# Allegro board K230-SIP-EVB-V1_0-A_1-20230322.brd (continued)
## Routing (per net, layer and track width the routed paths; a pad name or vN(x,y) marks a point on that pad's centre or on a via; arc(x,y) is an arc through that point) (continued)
VDD_5V: length 76.6
  TOP w0.305: v1(60.2,67.92) 60.35,68.07 61.09,68.07 ; v1(50.93,85.34) 50.55,85.72 R137.1 ; C145.1 v1(34.04,28.07) 34.04,28.45 34.58,29 U16.1 ; R35.2 v1(22.86,17.14) ; U6.3 45.97,27.82 ; R42.1 v1(10.92,47.75) ; R14.1 50.29,25.15 v1(50.16,25.02) ; R43.2 v1(10.92,52.07) ; v1(4.45,23.24) R3.1 ; R30.1 v1(40.39,26.29) ; U8.3 16.38,49.28 ; U30.6 60.02,129.34 v1(59.69,129.67) ; R15.1 v1(50.16,28.32) ; C284.2 v1(57.91,129.67) ; U15.4 37.97,45.66 v1(38.73,44.89) 38.93,44.7 C137.1 ; U9.3 65.65,65.28 ; R266.2 54.61,130.3 ; R5.1 64.26,28.96 ; U7.3 25.65,22.47 ; C283.2 v1(61.47,129.67) ; R28.2 v1(40.39,30.61)
  TOP w0.381: R8.2 v1(68.71,45.85) ; U27.5 v1(72.07,56.05) C273.2 ; R162.1 v1(70.17,53.21)
  ART03 w0.381: v1(60.2,67.92) 60.99,67.92 64.26,64.64 v1(64.26,63.88)
  BOTTOM w0.305: R23.2 53.34,46.11 ; v1(38.73,44.89) 39.37,44.26 39.37,41.53 38.99,41.15 38.99,30.81 ; U31.6 59.36,129.34 v1(59.69,129.67)
  BOTTOM w0.381: v1(50.93,85.34) 50.93,80.39 51.82,79.5 51.82,75.82 54.1,73.53 60.33,73.53 60.83,73.03 60.83,68.55 v1(60.2,67.92)
  vias: v1(9.14,117.47) v1(9.14,116.46) v1(14.86,47.75) v1(14.86,46.74) v1(14.86,45.47) v1(17.91,28.83) v1(17.91,27.94) v1(27.43,21.08) v1(28.7,21.08) v1(30.48,21.08) v1(33.91,18.16) v1(33.91,16.89) v1(33.91,15.62) v1(34.92,16.89) v1(44.58,26.42) v1(44.58,25.4) v1(44.58,24.38) v1(53.21,25.65) v1(53.21,24.64) v1(54.23,130.56) v1(54.23,46.1) v1(54.23,44.83) v1(54.23,43.56) v1(54.23,25.65) v1(54.23,24.64) v1(55.24,24.64) v1(55.5,130.56) v1(61.47,128.65) v1(64.26,62.87) v1(64.64,28.83) v1(64.64,27.69) v1(64.64,26.67) v1(65.02,45.09) v1(65.02,43.81) v1(65.02,42.55) v1(65.28,62.87)
VDD_5V_O: length 2.2
  TOP w0.305: J22.3 6.75,89.91 ; J22.4 6.76,90.41
  vias: v1(7.87,122.43) v1(7.87,121.16) v1(7.87,119.89) v1(49.53,135.89) v1(49.53,134.87) v1(50.93,135.89) v1(50.93,134.87)
3D_CTRL_IN: length 93.9
  TOP w0.076: 27.34,74.93 27.34,75.46 U19.P15
  TOP w0.127: J21.49 44.76,128.6 44.96,128.4 v1(47.88,128.4) ; 27.34,74.93 27.34,74.71 26.92,74.3 25.72,74.3 v3(24.89,75.12)
  ART03 w0.127: v3(24.89,75.12) 24.51,75.5 24.51,78.61 22.61,80.52 22.61,83.82 23.76,84.98 23.76,98.82 25.7,100.76 50.72,100.76 54.48,104.52 54.48,121.79 v1(47.88,128.4)
3D_CTRL_OUT1: length 94.1
  TOP w0.076: U19.P16 27.67,74.53 27.51,74.38
  TOP w0.127: v3(24.89,74.47) 25.45,73.91 27.05,73.91 27.51,74.38 ; v1(47.88,127.25) 45.59,127.25 44.26,128.59 J21.47
  ART03 w0.127: v3(24.89,74.47) 24.16,75.2 24.16,78.58 22.1,80.64 22.1,84.58 23.48,85.97 23.48,99.05 25.53,101.09 50.55,101.09 54.1,104.65 54.1,121.03 v1(47.88,127.25)
3D_CTRL_OUT2: length 105.3
  TOP w0.076: U19.P13 27.34,76.76 25.8,76.76
  TOP w0.127: J21.46 43.76,132.9 44.07,132.59 v1(44.2,132.59) ; v1(6.6,82.04) 6.6,76.07 8.38,74.3 11.43,74.3 12.06,73.66 13.97,73.66 14.76,74.45 22.89,74.45 25.2,76.76 25.8,76.76
  ART03 w0.127: v1(44.2,132.59) 43.94,132.84 40.77,132.84 38.77,130.85 38.77,116.75 36.45,114.43 26.54,114.43 13.34,101.22 13.34,99.06 12.24,97.97 12.24,91.53 9.91,89.19 9.91,86.61 7.62,84.33 7.62,83.06 v1(6.6,82.04)
ADC0: length 12.7
  TOP w0.127: U19.A7 36.88,80.99 37.95,82.05 39.51,82.05 41.66,84.2 44.96,84.2 v1(46.1,85.34)
  BOTTOM w0.127: v1(46.1,85.34) 46.1,86.23
ADC1: length 10
  TOP w0.127: U19.A6 36.72,81.64 42.2,87.12 v1(42.93,87.12)
  BOTTOM w0.127: R230.1 v1(42.93,87.12)
ADC2: length 65.7
  TOP w0.076: U19.B6 35.79,81.96 36.32,81.96
  TOP w0.127: v1(55.24,97.54) 45.34,87.63 42.31,87.63 36.64,81.96 36.32,81.96
  ART03 w0.127: v1(48.01,131.7) 48.01,130.18 55.24,122.94 v1(55.24,97.54)
  BOTTOM w0.127: v1(48.01,131.7) 48.01,132.59 R178.2
BOOT_CTL0: length 57.6
  TOP w0.127: v1(73.41,57.91) 74.8,57.91 74.93,57.78 SW1.1 ; U19.C14 v3(35.14,76.11)
  ART03 w0.127: v3(35.14,76.11) 35.49,76.45 48.01,76.45 48.77,75.69 62.36,75.69 62.74,76.07 63.93,76.07 69.85,70.15 69.85,65.28 73.41,61.72 73.41,59.82 73.91,59.31 73.91,58.42 v1(73.41,57.91)
  BOTTOM w0.127: v1(73.41,57.91) 73.41,57.28 TVS3.2 74.55,57.02 R99.1
BOOT_CTL1: length 62.7
  TOP w0.076: U19.C15 35.14,75.46 35.14,74.93 35.26,74.81
  TOP w0.127: 35.26,74.81 36.03,74.04 45.85,74.04 v1(47.62,75.82) ; SW1.2 77.47,57.91 76.33,59.05 v1(73.41,59.05)
  ART03 w0.127: v1(73.41,59.05) 73.03,59.44 73.03,61.47 69.47,65.02 69.47,70.13 64.54,75.06 56.52,75.06 56.13,74.68 49.15,74.68 48.01,75.82 v1(47.62,75.82)
  BOTTOM w0.127: v1(73.41,59.05) 74.17,59.05 TVS2.2 77.09,57.02 R101.1
CC1: length 7.8
  TOP w0.127: J1.A5 74.08,12.7 74.68,13.3 v1(74.68,14.22) 74.68,15.11 74.09,15.7 J1.B5
  BOTTOM w0.127: R1.1 v1(74.68,14.22)
CC_T: length 10.8
  TOP w0.127: R193.1 68.83,107.31 TVS7.1 69.35,105.91 J27.B5 73.21,105.91 74.17,104.95 74.17,103.5 73.57,102.91 J27.A5
CLK24M_XIN: length 16.8
  TOP w0.127: U19.A15 36.61,75.79 36.92,75.48 44.54,75.48 47.75,78.69 47.75,80.64 R97.2
CLK24M_XOUT: length 17
  TOP w0.076: 36.32,75.46 35.79,75.46 U19.B15
  TOP w0.127: 36.32,75.46 36.55,75.46 36.93,75.08 44.98,75.08 48.39,78.49 48.39,80.01 R105.2
CTRL0: length 26.8
  TOP w0.127: R170.2 v1(58.42,122.05) 58.42,122.43 58.71,122.72 U30.1
  ART03 w0.127: J36.1 57.91,98.55 57.91,121.54 v1(58.42,122.05)
CTRL1: length 29.1
  ART03 w0.127: v1(61.21,122.43) 58.29,119.51 58.29,100.46 J36.2
  BOTTOM w0.127: R171.2 61.21,121.41 v1(61.21,122.43) 60.67,122.98 U31.1
DDR_VREF: length 9.3
  TOP w0.254: U19.H11 v3(31.89,78.06)
  BOTTOM w0.305: C241.1 32,77.94 32.75,77.19 32.75,75.2 33.27,74.68 33.27,73.41 C240.1 C300.2 R95.2 R98.1
DEBUG_DM: length 25.6
  TOP w0.114: J27.A7 73.26,104.41 73.41,104.27 73.41,103.52 73.29,103.41 J27.B7 71.34,103.41 71.28,103.47 66.47,103.47 v1(66.13,103.12) ; v1(63.25,114.7) 63.47,114.47 63.47,114.02 R188.1
  BOTTOM w0.114: v1(63.25,114.7) 63.45,114.49 63.45,110.94 64.77,109.62 64.77,103.78 65.22,103.33 65.92,103.33 v1(66.13,103.12) 66.46,103.46 66.88,103.46 66.99,103.35 U34.2
DEBUG_DP: length 25.3
  TOP w0.114: v1(66.13,104.14) 66.45,103.81 71.22,103.81 71.32,103.91 ; 71.32,103.91 71.12,104.11 71.12,104.78 71.25,104.91 J27.B6 ; 71.32,103.91 J27.A6 ; R187.1 63.82,114.24 63.82,114.47 64.04,114.7 v1(64.26,114.7)
  BOTTOM w0.114: U34.3 66.99,103.92 66.88,103.8 66.46,103.8 v1(66.13,104.14) 65.66,103.68 65.36,103.68 65.11,103.92 65.11,109.77 63.79,111.09 63.79,114.47 64.02,114.7 v1(64.26,114.7)
EN: length 6.2
  TOP w0.305: R57.1 C118.1 ; R57.1 28.96,45.09 29.83,45.96 U12.4 ; R57.1 R60.1 C115.1
EN_CORE_K210: length 37.6
  ART03 w0.305: v1(18.41,42.55) 18.41,30.99 15.88,28.45 15.88,13.34 J35.2
  BOTTOM w0.305: R64.1 v1(18.41,42.55)
EN_DDR_K210: length 50.5
  TOP w0.305: v1(28.07,27.69) 26.42,27.69 R231.1 ; J35.1 20.7,12.7 22.48,14.48 25.02,14.48 v1(28.07,17.53) ; v1(31.11,42.29) 31.24,42.16 40.39,42.16 40.89,42.67 R86.1
  ART03 w0.305: v1(28.07,17.53) v1(28.07,27.69) 28.07,28.83 30.35,31.11 30.35,41.53 v1(31.11,42.29)
GPIO7: length 27.9
  TOP w0.127: U19.M16 28.7,74.87 28.7,74.42 25.4,71.12 10.16,71.12 J34.3
GPIO8: length 28.1
  TOP w0.127: U19.N16 28.32,74.67 25.78,72.14 14.35,72.14 13.97,71.75 7.11,71.75 6.6,72.26 3.68,72.26 J34.8
GPIO20: length 17.3
  TOP w0.076: 32.54,85.09 32.54,84.71 32.42,84.58 32.13,84.58 31.78,84.24 U19.H2
  TOP w0.127: 32.54,85.09 32.54,87.32 33.38,88.15 33.38,96.76 34.42,97.8 34.42,98.81 34.92,99.31 R213.1
GPIO21: length 15.9
  TOP w0.127: U19.H1 31.57,88.35 32.38,89.17 32.38,98.42 R214.1
GPIO22: length 15.3
  TOP w0.127: U19.J1 30.92,88.62 31.69,89.39 31.69,99.63 R215.1
GPIO23: length 16.3
  TOP w0.076: U19.J2 30.92,84.38 31.24,84.71 31.24,85.34
  TOP w0.127: R216.1 32.02,99.2 32.02,89.29 31.24,88.52 31.24,85.34
GPIO24: length 80.3
  TOP w0.076: 31.89,85.09 31.89,84.68 31.79,84.58 31.47,84.58 31.24,84.35 31.24,83.91 U19.J3
  TOP w0.127: U21.6 47.66,117.44 47.5,117.6 44.2,117.6 43.94,117.35 43.94,113.54 43.31,112.9 v1(40.01,112.9) ; v1(33.53,98.55) 32.73,97.75 32.73,89.05 31.89,88.22 31.89,85.09
  BOTTOM w0.127: v1(40.01,112.9) 39.5,112.39 39.5,105.11 33.53,99.14 v1(33.53,98.55) 27.56,92.58 23.37,92.58 12.45,103.5 11.05,103.5 10.67,103.89 R222.2 10.67,107.25 Q3.2
GPIO24_3V3: length 44.5
  TOP w0.127: v1(44.58,113.54) R135.2
  ART03 w0.127: v1(44.58,113.54) 43.81,114.3 38.1,114.3 37.08,113.28 30.35,113.28 21.46,104.39 18.67,104.39 v1(15.56,101.28)
  BOTTOM w0.127: v1(15.56,101.28) 12.83,104.01 R223.2 12.83,105.73 Q1.1 12.51,107.31 Q3.3
GPIO25: length 46.6
  ART03 w0.127: v1(42.16,101.73) 50.67,101.73 53.72,104.78 53.72,120.52 v1(46.35,127.89)
  BOTTOM w0.127: R176.2 43.69,131.57 45.77,129.49 45.77,128.47 v1(46.35,127.89) ; R127.1 v1(42.16,101.73)
GPIO32: length 91
  TOP w0.127: U21.12 48.86,114.52 47.88,113.54 v1(46.74,113.54) ; R115.2 v1(8.64,74.93)
  ART03 w0.127: v1(46.74,113.54) 45.59,112.39 38.73,112.39 36.7,110.36 29.46,110.36 20.32,101.22 19.43,101.22 14.1,95.89 14.1,90.17 12.95,89.03 12.95,79.25 v1(8.64,74.93) 7.24,73.53 7.24,60.2 5.71,58.67 4.57,58.67 3.56,57.66 3.56,55.63 J38.1
GPIO32_1V8: length 15
  TOP w0.127: R133.1 v1(49.28,120.78)
  BOTTOM w0.127: v1(49.28,120.78) 47.24,122.81 47.24,132.21 R177.2
GPIO33: length 88.1
  TOP w0.127: v1(45.59,113.54) 46.23,114.17 47.88,114.17 48.46,114.75 U21.11 ; R116.2 v1(8.89,78.74)
  ART03 w0.127: v1(45.59,113.54) 45.09,113.03 42.29,113.03 41.66,113.67 38.35,113.67 35.94,111.25 29.34,111.25 20.07,101.98 19.18,101.98 13.54,96.34 13.54,90.58 12.19,89.23 12.19,82.04 v1(8.89,78.74) 6.48,76.33 6.48,62.74 3.81,60.07 3.81,59.44 2.54,58.17 J38.2
GPIO33_1V8: length 14.9
  TOP w0.127: R134.1 v1(48.01,120.78)
  BOTTOM w0.127: v1(48.01,120.78) 46.86,121.92 46.86,129.67 45.21,131.32 45.21,133.1 R174.2
GPIO34: length 80.9
  TOP w0.127: v1(38.99,111.76) 39.34,112.11 U20.12 ; R118.2 v1(8.64,72.39)
  ART03 w0.127: v1(38.99,111.76) 39.37,111.38 39.37,110.24 38.61,109.47 29.59,109.47 20.45,100.33 20.45,93.26 15.75,88.56 15.75,77.72 14.86,76.83 13.08,76.83 v1(8.64,72.39)
  BOTTOM w0.127: v1(8.64,72.39) 8.64,67.06 J34.1 6.22,62.36 6.22,58.29 J37.2
GPIO34_1V8: length 15.7
  TOP w0.127: J21.32 40.25,132.84 39.75,132.33 v2(38.99,132.33) ; R128.1 v1(40.64,120.78)
  BOTTOM w0.127: v2(38.99,132.33) 38.99,122.43 v1(40.64,120.78)
GPIO35: length 119
  TOP w0.127: R119.2 v1(8.64,73.66) ; v1(38.81,110.49) 38.48,110.82 38.48,113.16 38.94,113.61 U20.11
  ART03 w0.127: J32.1 5.33,25.65 5.33,28.07 4.45,28.96 4.45,53.98 J37.1 3.94,55.75 3.94,57.53 4.7,58.29 5.97,58.29 7.62,59.94 7.62,72.64 v1(8.64,73.66) 12.32,77.34 14.86,77.34 15.24,77.72 15.24,90.3 14.48,91.06 14.48,95.76 19.62,100.9 20.51,100.9 29.46,109.86 38.17,109.86 v1(38.81,110.49)
GPIO35_1V8: length 17.2
  TOP w0.127: J21.34 40.76,132.83 39.76,131.84 v2(37.72,131.84) ; R129.1 v1(39.37,120.78)
  BOTTOM w0.127: v2(37.72,131.84) 37.72,122.43 v1(39.37,120.78)
GPIO36: length 75
  TOP w0.127: v1(37.21,111.76) 37.21,112.52 38.54,113.85 U20.10 ; R120.2 v1(8.64,76.2)
  ART03 w0.127: J37.3 6.86,61.47 6.86,74.42 v1(8.64,76.2) 12.57,80.14 12.57,89.15 13.82,90.4 13.82,96.11 19.3,101.6 20.19,101.6 29.34,110.74 36.2,110.74 v1(37.21,111.76)
GPIO36_1V8: length 19
  TOP w0.127: R130.1 v1(38.1,120.78) ; v2(36.32,131.44) 40.13,131.44 41.26,132.57 J21.36
  BOTTOM w0.127: v1(38.1,120.78) 37.34,121.54 37.34,130.43 v2(36.32,131.44)
GPIO37: length 77.1
  TOP w0.127: v1(7.87,78.74) 9.14,77.47 R121.2 ; v1(36.2,112.52) 38.14,114.46 U20.9
  ART03 w0.127: J38.3 4.06,61.21 4.32,61.21 6.1,62.99 6.1,76.96 v1(7.87,78.74) 11.3,82.17 11.3,89.15 13.11,90.96 13.11,96.8 19.43,103.12 20.7,103.12 30.1,112.52 v1(36.2,112.52)
GPIO37_1V8: length 17.4
  TOP w0.127: R131.1 v1(36.83,120.78)
  BOTTOM w0.127: R175.2 39.64,132.85 36.83,132.85 35.88,131.9 35.88,121.73 v1(36.83,120.78)
GPIO38: length 51.2
  TOP w0.127: U19.E3 v3(33.84,83.26)
  ART03 w0.102: v3(33.84,83.26) 34.17,83.59 34.17,84.31
  ART03 w0.127: 34.17,84.31 34.17,89.03 v1(35.81,90.68)
  BOTTOM w0.127: v1(35.81,90.68) 24,90.68 16.76,83.44 16.76,76.45 13.21,72.9 5.84,72.9 J34.9
GPIO39: length 52.1
  TOP w0.127: v1(35.56,91.95) 35.32,91.71 35.32,87.89 34.17,86.74 U19.D1
  BOTTOM w0.127: v1(35.56,91.95) 35.31,91.69 23.75,91.69 16,83.95 16,77.34 14.86,76.2 12.45,76.2 11.81,76.83 7.24,76.83 6.35,77.72 3.56,77.72 J34.14
GPIO40: length 18.3
  TOP w0.076: 35.14,85.13 35.14,84.67 35.05,84.58 34.67,84.58 34.32,84.24 U19.D2
  TOP w0.127: 35.14,85.13 35.14,86.46 37.59,88.91 37.59,92.96 38.81,94.18 38.81,98.76 R110.1
GPIO41: length 16.9
  TOP w0.127: R111.1 38.35,99.44 38.35,97.66 37.82,97.13 37.82,96.11 36.83,95.12 36.83,93.47 37.27,93.03 37.27,89.06 34.82,86.6 U19.C1
GPIO44: length 17.2
  TOP w0.127: R112.1 39.09,97.89 39.09,93.95 37.9,92.76 37.9,88.76 35.47,86.33 U19.B1
GPIO45: length 19
  TOP w0.076: U19.C2 35.04,84.24 35.38,84.58 35.73,84.58 35.79,84.64 35.79,85.22
  TOP w0.127: R113.1 39.37,97.03 39.37,93.75 38.23,92.61 38.23,88.63 35.79,86.19 35.79,85.22
GPIO48: length 18
  TOP w0.127: U19.D3 v3(33.84,83.91)
  ART03 w0.127: v1(36.32,92.71) 36.32,91.95 33.84,89.47 v3(33.84,83.91)
  BOTTOM w0.127: R218.1 35.69,99.06 35.69,93.34 v1(36.32,92.71)
GPIO49: length 18.2
  TOP w0.127: U19.C3 v3(34.49,83.91)
  ART03 w0.127: v1(37.47,93.85) 36.83,93.22 36.83,91.69 36.32,91.19 36.32,90.42 34.49,88.59 v3(34.49,83.91)
  BOTTOM w0.127: R219.1 36.83,99.06 36.83,94.49 v1(37.47,93.85)
GPIO59: length 89.7
  TOP w0.127: U19.P4 v3(27.34,83.26)
  ART03 w0.127: v3(27.34,83.26) 26.92,83.68 26.92,84.2 28.57,85.85 28.57,87 28.96,87.38 28.96,94.87 34.54,100.46 50.93,100.46 54.86,104.39 54.86,122.68 47.37,130.18 47.37,131.7 45.85,133.22 36.45,133.22 v1(35.73,132.5)
  BOTTOM w0.127: v1(35.73,132.5) 36.7,133.48 R173.2
GPIO60: length 23.7
  TOP w0.127: U19.N3 v3(27.99,83.91)
  ART03 w0.127: v1(38.32,96.65) 36.54,94.87 32.47,94.87 30.86,93.26 30.86,86.78 v3(27.99,83.91)
  BOTTOM w0.127: R114.1 39.88,98.21 v1(38.32,96.65)
GPIO61: length 23
  TOP w0.127: R117.1 37.59,97.66 36.32,96.39 v1(36.32,95.89) ; U19.P3 v3(27.34,83.91)
  ART03 w0.127: v1(36.32,95.89) 32.26,95.89 30.1,93.73 30.1,86.87 27.34,84.11 v3(27.34,83.91)
HP_INSERT_DET: length 97
  TOP w0.127: v1(62.1,116.71) 67.82,116.71 68.33,116.2 69.47,116.2 69.98,116.71 R169.1
  BOTTOM w0.127: J34.12 3.56,77.22 6.22,77.22 7.75,75.69 15.11,75.69 16.38,76.96 16.38,83.69 24,91.31 36.07,91.31 39.24,94.49 39.24,95.82 43.12,99.69 43.12,105.22 46.35,108.46 57.66,108.46 62.1,112.9 v1(62.1,116.71)
HPOUTL: length 57.1
  TOP w0.076: U19.B2 35.67,84.24 36,84.56 36.3,84.56 36.51,84.77
  TOP w0.127: v1(58.93,118.75) 53.94,113.75 53.94,104.61 48.55,99.23 43.85,99.23 40.89,96.27 40.89,93.64 38.86,91.61 38.86,88.46 36.58,86.17 36.58,84.84 36.51,84.77 ; C281.1 v1(62.23,123.7)
  ART03 w0.127: v1(62.23,123.7) 62.23,122.68 58.93,119.38 v1(58.93,118.75)
  BOTTOM w0.127: C309.1 58.42,119.25 v1(58.93,118.75)
HPOUTR: length 52.5
  TOP w0.127: C279.1 62.36,120.78 61.72,120.14 C307.1 60.33,119.51 60.33,119.25 54.23,113.16 54.23,104.39 48.7,98.87 44,98.87 41.22,96.09 41.22,93.55 39.16,91.49 39.16,88.35 36.84,86.03 36.84,84.7 36.37,84.24 U19.A2
HSYNC0: length 133.8
  TOP w0.127: v1(45.26,128.91) J21.51
  ART03 w0.127: J34.11 5.08,77.09 10.92,82.93 10.92,89.28 12.83,91.19 12.83,97.41 14.22,98.81 14.22,101.09 18.8,105.66 22.23,105.66 30.23,113.67 36.7,113.67 41.27,118.24 41.27,122.05 39.5,123.83 39.5,130.43 41.15,132.08 43.43,132.08 45.26,130.26 v1(45.26,128.91) 45.26,127.72 51.56,121.41 51.56,103.63 50.55,102.62 v1(50.29,102.62)
  BOTTOM w0.127: v1(50.29,102.62) 50.29,94.23 45.09,89.03 R229.2
IIC0_SCL: length 45
  TOP w0.127: J21.38 41.76,132.49 42.29,131.95 v1(42.29,131.57)
  ART03 w0.127: v1(39.88,101.73) 42.67,104.52 46.99,104.52 48.41,105.94 48.41,118.59 41.27,125.73 41.27,130.56 v1(42.29,131.57)
  BOTTOM w0.127: v1(42.29,131.57) 41.4,132.46 R179.2 ; R114.2 v1(39.88,101.73)
IIC0_SDA: length 47.7
  TOP w0.127: v1(45.21,104.01) 40.26,104.01 37.59,101.35 R117.2 ; J21.40 42.26,132.88 43.18,131.95 v1(43.18,131.57)
  ART03 w0.127: v1(45.21,104.01) 46.99,104.01 48.7,105.73 48.7,118.81 41.66,125.86 41.66,130.05 v1(43.18,131.57)
  BOTTOM w0.127: R180.2 42.55,132.21 v1(43.18,131.57)
IIC1_SCL: length 113.3
  TOP w0.127: R269.1 67.82,52.45 v1(66.55,53.72) ; v1(44.2,126.87) 43.26,127.81 J21.43 ; v1(49.28,103.76) 48.64,103.12 41.66,103.12 40.39,101.85 40.39,101.35 R110.2
  ART03 w0.127: v1(44.2,126.87) 50.8,120.27 50.8,105.28 v1(49.28,103.76)
  BOTTOM w0.127: R181.2 43.69,126.36 v1(44.2,126.87) ; v1(49.28,103.76) 49.91,103.12 50.67,103.12 50.93,102.87 50.93,95.76 55.83,90.85 55.83,77.77 57.53,76.07 64.22,76.07 66.25,74.04 66.25,69.55 65.91,69.22 63.88,69.22 62.82,68.15 62.82,57.7 66.55,53.98 v1(66.55,53.72)
IIC1_SDA: length 117.9
  TOP w0.127: R111.2 39.24,101.35 39.24,101.98 40.77,103.5 47.62,103.5 48.39,104.27 49.78,104.27 v1(50.29,103.76) ; v1(66.61,54.93) 68.36,53.17 68.36,48.55 R268.1 ; J21.45 43.76,128.33 v1(44.07,128.02)
  ART03 w0.127: v1(50.29,103.76) 51.18,104.65 51.18,120.9 v1(44.07,128.02)
  BOTTOM w0.127: R182.2 44.83,127.25 v1(44.07,128.02) ; v1(66.61,54.93) 66.1,54.93 63.25,57.78 63.25,68.07 64.01,68.83 66.04,68.83 66.55,69.34 66.55,74.17 64.26,76.45 57.78,76.45 56.32,77.91 56.32,91 51.37,95.95 51.37,103.06 50.67,103.76 v1(50.29,103.76)
IIC3_SCL: length 39.4
  TOP w0.127: J21.41 42.76,127.37 v1(42.26,126.87) ; v1(44.07,102.62) 42.16,102.62 41.53,101.98 41.53,101.35 R112.2
  ART03 w0.127: v1(42.26,126.87) 42.26,125.77 49.02,119 49.02,105.54 46.86,103.38 44.83,103.38 v1(44.07,102.62)
  BOTTOM w0.127: v1(42.26,126.87) 42.55,126.58 R183.2
IIC3_SDA: length 39.6
  TOP w0.127: R113.2 43.43,100.84 v1(45.21,102.62) ; v1(42.26,127.89) J21.39
  ART03 w0.127: v1(45.21,102.62) 46.61,102.62 49.4,105.41 49.4,119.38 48.64,120.14 48.64,121.5 v1(42.26,127.89)
  BOTTOM w0.127: R184.2 41.4,127.04 v1(42.26,127.89)
IIC4_SCL: length 106.8
  TOP w0.127: R271.1 56.64,43.81 55.12,42.29 43.26,42.29 42.42,41.45 20.52,41.45 18.67,43.31 13.55,43.31 9.23,47.62 v1(6.35,47.62) ; v1(5.33,92.2) 5.54,92.41 J22.8
  BOTTOM w0.127: R185.2 v1(5.33,92.2) 5.33,90.63 1.14,86.44 1.14,67.44 J34.4 3.56,65.02 3.56,50.42 v1(6.35,47.62)
IIC4_SDA: length 106.4
  TOP w0.127: v1(5.33,93.34) 5.77,92.91 J22.9 ; v1(6.35,48.64) 8.65,48.64 13.65,43.64 18.81,43.64 20.69,41.76 42.14,41.76 43.05,42.67 54.74,42.67 55.5,43.43 R270.1
  BOTTOM w0.127: v1(6.35,48.64) 3.94,51.05 3.94,67.18 J34.6 1.52,69.6 1.52,86.11 5.84,90.42 5.84,92.84 v1(5.33,93.34) R186.2
INA226_0V8+: length 109
  TOP w0.305: v1(10.92,48.77) C78.2 R41.2 ; 45.72,1.91 44.32,3.3 44.32,4.95 41.4,7.87 12.7,7.87 v1(10.92,6.1)
  ART03 w0.305: v1(15.75,57.78) 14.48,57.78 12.06,55.37 12.06,47.37 9.91,45.21 9.91,7.11 v1(10.92,6.1) ; v1(10.92,48.77) 11.56,49.4 11.56,55.75 14.86,59.05 v1(15.75,59.05)
INA226_0V8-: length 87.5
  TOP w0.305: 43.18,1.91 41.91,3.17 41.91,5.33 39.88,7.37 13.34,7.37 v1(12.06,6.1)
  ART03 w0.305: v1(12.06,6.1) 10.54,7.62 10.54,25.91 11.56,26.92 11.56,45.97 12.57,46.99 12.57,54.99 v1(13.97,56.39)
INA226_1V8IO+: length 104.1
  TOP w0.305: 61.09,65.79 61.09,64.77 v1(60.07,64.77)
  ART03 w0.254: 37.34,5.58 37.06,5.3 37.06,3.58 37.47,3.17 39.37,3.17 40.64,1.91
  ART03 w0.305: v1(63.75,72.9) 63.5,72.64 63.5,68.88 63.2,68.58 54.37,68.58 53.72,67.93 53.72,59.94 49.66,55.88 49.66,41.78 42.04,34.16 42.04,25.02 38.73,21.72 38.73,6.97 37.34,5.58
  BOTTOM w0.305: v1(60.07,64.77) 61.47,66.17 61.47,73.41 v1(63.63,75.56)
INA226_1V8IO-: length 83.7
  ART03 w0.254: 36.96,6.22 36.6,5.87 36.6,3.4 38.1,1.91
  ART03 w0.305: 36.96,6.22 38.1,7.37 38.1,21.97 41.53,25.4 41.53,34.42 48.13,41.02 48.13,55.24 53.21,60.33 53.21,68.07 54.23,69.09 58.33,69.09 60.07,70.83 v1(62.1,70.83)
INA226_AVDDMIPI+: length 56.6
  TOP w0.305: 35.56,4.45 33.15,6.86 17.53,6.86 v1(16.89,6.22) ; R68.1 14.99,36.83
  TOP w0.381: R66.1 v1(17.14,38.73)
  ART03 w0.305: v1(16.89,6.22) 14.86,8.26 14.86,29.34 15.75,30.23 15.75,37.34 v1(17.14,38.73)
INA226_AVDDMIPI-: length 55.1
  TOP w0.305: v1(17.91,6.22) 31.24,6.22 33.02,4.45
  TOP w0.381: R66.2 v1(17.14,41.53)
  ART03 w0.305: v1(17.91,6.22) 15.37,8.76 15.37,29.08 16.51,30.23 16.51,36.96 17.78,38.23 17.78,40.89 v1(17.14,41.53)
INA226_CORE0+: length 35.7
  TOP w0.305: v1(45.97,54.36) 46.61,54.99 46.61,57.28 R25.1 ; v1(40.39,27.3) C54.2 R29.2
  ART03 w0.305: v1(40.39,27.3) 41.02,27.94 41.02,37.21 v1(43.56,39.75) ; v1(44.7,39.75) 45.59,40.64 45.59,53.98 v1(45.97,54.36)
INA226_CORE0-: length 26.6
  TOP w0.305: v1(45.97,55.75) 45.97,59.31 R26.1
  ART03 w0.305: v1(45.97,55.75) 46.86,54.86 46.86,40.64 v1(43.31,37.08)
INA226_CORE+: length 72.2
  TOP w0.305: 50.29,55.24 50.29,49.66 50.81,49.14 U5.8
  ART03 w0.305: v1(50.04,58.42) 44.83,58.42 44.2,57.78 44.2,54.23 43.01,53.05 43.01,50.51 41.4,48.9 41.4,40.26 37.59,36.45 37.59,26.8 32.77,21.97 32.77,8.38 30.48,6.1 30.48,4.45
INA226_CORE-: length 67.9
  ART03 w0.305: v1(50.04,61.47) 47.12,61.47 43.56,57.91 43.56,54.36 42.5,53.3 42.5,50.76 40.89,49.15 40.89,40.51 37.08,36.7 37.08,28.85 32.18,23.95 32.18,8.69 27.94,4.45
INA226_DDR_CORE+: length 59.4
  TOP w0.305: R62.1 23.11,51.44
  ART03 w0.305: 17.78,4.45 14.22,8 14.22,30.1 14.86,30.73 14.86,32 14.22,32.64 14.22,50.42 17.02,53.21 22.48,53.21 v1(23.37,52.32)
INA226_DDR_CORE-: length 59.6
  ART03 w0.305: 15.24,4.45 15.24,6.1 13.59,7.75 13.59,50.55 17.53,54.48 19.94,54.48 v1(23.37,57.91)
INA226_DDR_DRAM+: length 56
  TOP w0.305: R85.1 43.81,51.44
  ART03 w0.305: 35.56,1.91 34.42,3.05 34.42,5.08 37.47,8.13 37.47,23.75 39.6,25.88 39.6,36.8 43.09,40.3 43.09,49.06 44.2,50.16 v1(44.2,52.58)
INA226_DDR_DRAM-: length 61.9
  ART03 w0.305: v1(45.09,57.78) 45.09,54.36 43.5,52.77 43.5,50.15 42.62,49.28 42.62,40.59 39.1,37.07 39.1,26.15 36.58,23.62 36.58,11.68 35.05,10.16 35.05,8.64 31.75,5.33 31.75,3.17 33.02,1.91
INA226_DDR_IO0+: length 24.1
  TOP w0.305: R77.1 35.81,35.05 ; R74.1 39.75,54.99 v1(39.12,55.63)
  ART03 w0.305: v1(36.07,35.31) 35.43,35.94 35.43,51.05 38.23,53.85 38.23,54.74 v1(39.12,55.63)
INA226_DDR_IO0-: length 17.7
  TOP w0.305: v1(40.13,55.63) 40.13,56.39 R75.1
  ART03 w0.305: v1(36.83,40.64) 37.85,41.66 37.85,45.97 39.24,47.37 39.24,54.74 v1(40.13,55.63)
INA226_DDR_IO+: length 60.4
  TOP w0.381: R71.1 38.1,53.46
  ART03 w0.254: 27.3,5.46 26.87,5.03 26.87,3.73 27.43,3.17 29.21,3.17 30.48,1.91
  ART03 w0.305: v1(37.47,54.48) 34.04,51.05 34.04,35.05 33.4,34.42 33.4,27.05 31.62,25.27 31.62,16.13 29.72,14.22 29.72,7.87 27.3,5.46
INA226_DDR_IO-: length 60
  ART03 w0.254: 27.94,1.91 26.47,3.38 26.47,5.51 26.86,5.91
  ART03 w0.305: v1(37.47,56.77) 33.53,52.83 33.53,42.93 32.77,42.16 32.77,27.18 31.11,25.53 31.11,17.91 27.3,14.1 27.3,6.35 26.86,5.91
INA226_KPU0+: length 36.8
  TOP w0.305: R10.1 v1(58.55,59.31)
  TOP w0.381: 60.83,26.29 v1(61.72,26.29)
  ART03 w0.305: v1(61.72,26.29) 60.83,27.18 60.83,29.21 58.04,32 v1(58.04,35.56) ; v1(53.72,37.08) 54.86,38.23 54.86,41.66 55.88,42.67 55.88,55.75 57.28,57.15 57.28,58.04 v1(58.55,59.31)
INA226_KPU0-: length 22
  TOP w0.305: R11.1 v1(58.55,60.2)
  ART03 w0.305: v1(58.55,60.2) 59.18,59.56 59.18,57.28 56.39,54.48 56.39,40.89 v1(56.64,40.64)
INA226_KPU+: length 70.6
  TOP w0.305: U3.8 61.22,48.13 59.92,49.43 59.92,54.08
  ART03 w0.305: v1(60.71,57.4) 60.71,56.26 57.4,52.96 57.4,41.91 57.78,41.53 57.78,39.37 54.36,35.94 51.94,35.94 49.58,33.58 49.58,24.43 41.91,16.76 41.91,5.71 40.64,4.45
INA226_KPU-: length 68.3
  ART03 w0.305: 38.1,4.45 41.27,7.62 41.27,17.27 48.39,24.38 48.39,36.07 48.77,36.45 54.1,36.45 57.28,39.62 57.28,41.27 56.9,41.66 56.9,53.21 60.07,56.39 v1(60.07,60.2)
INA226_MIPI1V8+: length 54.8
  TOP w0.305: R58.1 30.61,51.44
  ART03 w0.305: v1(30.99,52.58) 27.56,49.15 27.56,28.19 26.8,27.43 26.8,17.27 24.77,15.24 24.77,7.37 24.13,6.73 24.13,3.17 22.86,1.91
INA226_MIPI1V8-: length 57
  ART03 w0.305: 20.32,1.91 21.72,3.3 21.72,13.21 26.16,17.65 26.16,21.84 25.53,22.48 25.53,30.1 26.29,30.86 v1(26.29,55.88)
INA226_PLL+: length 74.3
  ART03 w0.305: v1(56.39,64.64) 58.29,64.64 61.85,61.09 61.85,55.88 59.82,53.85 59.82,39.62 55.12,34.92 52.45,34.92 51.56,34.04 51.56,21.21 46.35,16 46.35,5.08 J30.1
  BOTTOM w0.305: R81.1 v1(56.39,64.64) C151.1
INA226_PLL-: length 76.1
  ART03 w0.305: v1(54.36,67.73) 54.36,65.79 57.02,63.12 58.55,63.12 61.34,60.33 61.34,56.13 58.62,53.42 58.62,39.32 54.74,35.43 52.2,35.43 50.93,34.16 50.93,24.77 43.18,17.02 J30.3
  vias: v1(52.45,69.72) v1(53.34,69.72)
INA226_USB+: length 44.6
  TOP w0.305: 10.03,16.38 11.3,15.11 21.34,15.11 21.72,15.49 23.62,15.49 25.15,17.02 R36.2 C65.2 ; v1(13.21,6.1) 13.72,5.59 21.72,5.59 22.86,4.45
  ART03 w0.305: v1(11.94,20.83) 11.18,20.07 11.18,8.13 v1(13.21,6.1)
INA226_USB-: length 21.2
  ART03 w0.305: v1(12.06,16.89) 11.68,16.51 11.68,8.64 13.84,6.48 13.84,3.94 14.48,3.3 19.18,3.3 20.32,4.45
JTAG_RST: length 62
  TOP w0.127: v1(6.48,34.16) R123.2 2.54,34.92 ; U19.N13 v3(27.99,76.76)
  ART03 w0.102: 27.53,75.81 27.67,75.94 27.67,76.44 v3(27.99,76.76)
  ART03 w0.127: v1(6.48,34.16) 5.71,34.92 5.71,52.07 6.86,53.21 6.86,56.77 12.19,62.1 12.19,67.78 17.61,73.19 25.59,73.19 27.18,74.78 27.18,75.45 27.53,75.81
JTAG_TCK: length 50.6
  TOP w0.127: J7.3 R126.2 6.48,45.59 6.86,45.97 v1(8,45.97) ; U19.L14 v3(29.29,76.11)
  ART03 w0.127: v1(8,45.97) 10.16,48.13 10.16,57.53 14.22,61.59 14.22,67.06 16.13,68.96 19.05,68.96 19.81,68.2 22.86,68.2 28.82,74.16 28.82,75.63 v3(29.29,76.11)
JTAG_TDI: length 53.9
  TOP w0.127: U19.N15 v3(27.99,75.46) ; R125.2 v1(6.48,40.89) 5.59,40.01 J7.5
  ART03 w0.127: v3(27.99,75.46) 27.99,74.46 24.65,71.12 16.89,71.12 13.21,67.44 13.21,61.85 7.65,56.29 7.65,52.73 6.99,52.07 6.99,49.4 7.37,49.02 7.37,47.37 6.86,46.86 6.86,41.27 v1(6.48,40.89)
JTAG_TDO: length 51.7
  TOP w0.127: J7.4 v1(6.35,42.55) ; U19.N14 v3(27.99,76.11)
  ART03 w0.102: 27.56,75.06 27.56,75.49 27.99,75.92 v3(27.99,76.11)
  ART03 w0.127: v1(6.35,42.55) 6.35,46.86 6.99,47.5 6.99,48.9 6.6,49.28 6.6,52.2 7.37,52.96 7.37,56.52 12.83,61.98 12.83,67.56 17.4,72.14 25.26,72.14 27.56,74.43 27.56,75.06
JTAG_TMS: length 56.6
  TOP w0.127: v1(6.48,38.23) R124.2 J7.6 ; U19.M14 v3(28.64,76.11)
  ART03 w0.127: v3(28.64,76.11) 28.45,75.92 28.45,74.51 24.68,70.74 17.15,70.74 13.72,67.31 13.72,61.85 9.65,57.78 9.65,48.64 7.24,46.23 7.24,38.99 v1(6.48,38.23)
K230_RSTN: length 76.6
  TOP w0.127: K1.2 v1(75.56,44.32) ; U19.C12 v3(35.14,77.41)
  ART03 w0.127: v3(35.14,77.41) 48.45,77.41 49.38,76.48 61.87,76.48 62.36,76.96 64.17,76.96 71.48,69.66 71.48,65.05 74.3,62.23 74.3,60.45 75.06,59.69 75.06,50.67 75.56,50.16 v1(75.56,44.32)
  BOTTOM w0.127: R92.2 R90.2 R89.2 C238.2 76.45,47.37 TVS1.1 76.45,45.21 v1(75.56,44.32)
LMICN: length 73.1
  TOP w0.127: v2(56.39,110.11) 56.39,103.25 49.28,96.14 49.28,93.09 44.92,88.73 41.74,88.73 41.27,88.27 41.27,87.88 38.99,85.59 38.99,84.71 36.57,82.29 U19.A5 ; v1(69.72,133.6) 69.72,135.76 69.98,136.02 C275.1
  ART03 w0.127: v2(56.39,110.11) 56.9,110.62 56.9,121.79 63.88,128.78 63.88,132.46 65.02,133.6 v1(69.72,133.6)
LMICP: length 73.8
  TOP w0.076: U19.B5 35.79,82.61 36.32,82.61
  TOP w0.127: C277.1 v1(71.5,134.11) ; 36.32,82.61 36.5,82.61 38.6,84.72 38.6,85.75 40.89,88.04 40.89,88.39 41.53,89.03 44.7,89.03 48.9,93.22 48.9,96.27 55.94,103.31 55.94,110.55 v2(56.39,111)
  ART03 w0.127: v2(56.39,111) 56.39,121.79 63.5,128.9 63.5,132.72 64.9,134.11 v1(71.5,134.11)
M_CLK1: length 99
  TOP w0.076: 26.16,78.06 27.34,78.06 U19.P12
  TOP w0.127: 26.16,78.06 25.23,78.06 22.86,75.69 14.1,75.69 12.95,76.83 8.51,76.83 7.24,78.11 7.24,82.55 v1(6.6,83.19) ; J21.26 38.75,132.99 38.23,132.46 37.21,132.46 v2(36.96,132.21)
  ART03 w0.127: v1(6.6,83.19) 7.11,83.69 7.11,84.58 9.4,86.87 9.4,89.53 11.68,91.82 11.68,98.17 12.83,99.31 12.83,101.47 26.29,114.94 36.2,114.94 37.72,116.46 37.72,119.76 37.47,120.02 37.47,130.94 36.96,131.44 v2(36.96,132.21)
M_CLK2: length 89.7
  TOP w0.127: J21.31 40.25,129.42 40.64,129.03 40.64,128.27 v1(40.13,127.76) ; U19.L13 v3(29.29,76.76)
  ART03 w0.102: v3(29.29,76.76) 28.7,77.36 27.79,77.36 26.42,75.98 26.42,75.73
  ART03 w0.127: v1(40.13,127.76) 40.77,127.13 40.77,124.21 47.9,117.07 47.9,106.2 46.74,105.03 28.7,105.03 22.97,99.3 22.97,85.97 21.72,84.71 21.72,76.96 24.56,74.12 25.6,74.12 26.42,74.93 26.42,75.73
M_CLK3: length 89.5
  TOP w0.127: U19.M13 v3(28.64,76.76) ; v1(40.14,126.75) 41.26,127.87 J21.35
  ART03 w0.102: 26.8,75.73 26.8,76.03 27.86,77.1 28.3,77.1 v3(28.64,76.76)
  ART03 w0.127: 26.8,75.73 26.8,74.94 25.64,73.79 24.26,73.79 21.34,76.71 21.34,84.96 22.47,86.09 22.47,99.56 28.57,105.66 46.61,105.66 47.37,106.43 47.37,116.84 40.14,124.08 v1(40.14,126.75)
MICBIAS: length 78.2
  TOP w0.254: v1(62.1,117.73) 55.38,111.01 55.38,103.64 49.28,97.54 44.58,97.54 42.42,95.38 42.42,92.99 40.26,90.83 v1(40.26,90.04) 40.26,88.01 38.23,85.98 38.23,84.84 36.33,82.94 U19.A4
  TOP w0.305: R172.2 C286.2 v1(64.9,131.95) ; R165.1 v1(73.53,133.22)
  ART03 w0.305: v1(73.53,133.22) 72.9,132.59 69.85,132.59 69.49,132.23 ; 69.49,132.23 69.47,132.21 69.47,125.09 v1(62.1,117.73) ; 69.49,132.23 69.14,132.59 65.53,132.59 v1(64.9,131.95)
MIPI_CSI0_CLK0_N: length 77.3
  TOP w0.114: U19.P1 27.68,84.9 27.68,85.32 25.78,87.23 25.78,89.07 25.91,89.2 25.98,89.2 26.11,89.34 26.11,89.53 25.98,89.66 25.91,89.66 25.78,89.79 25.78,89.98 25.91,90.12 25.98,90.12 26.11,90.25 26.11,90.44 25.98,90.58 25.91,90.58 25.78,90.71 25.78,91.84 26.19,92.25 26.19,113.08 26.36,113.25 29.78,113.25 30.2,113.67 30.2,114.24 29.77,114.66 28.18,114.66 27.98,114.86 27.98,115.15 28.18,115.35 29.8,115.35 30.2,115.75 30.2,116.32 29.8,116.72 28.18,116.72 28,116.9 28,122.87 27.69,123.19 26.27,123.19 26.06,123.4 26.06,123.83 26.23,124 28.81,124 29.21,124.4 29.21,124.97 28.81,125.37 27.25,125.37 27.05,125.57 27.05,125.85 27.25,126.06 29.44,126.06 29.84,126.46 29.84,127.03 29.44,127.43 27.58,127.43 27.38,127.63 27.38,127.91 27.58,128.11 29.44,128.11 29.84,128.51 29.84,129.59 29.44,129.99 28.94,129.99 28.64,130.3 28.64,131.03 28.97,131.36 30.33,131.36 30.46,131.22 30.46,131.02 30.6,130.89 30.79,130.89 30.92,131.02 30.92,131.22 31.06,131.36 31.25,131.36 31.38,131.22 31.38,131.02 31.51,130.89 31.7,130.89 31.84,131.02 31.84,131.22 31.97,131.36 32.62,131.36 32.75,131.23 J21.1
MIPI_CSI0_CLK0_P: length 77.3
  TOP w0.114: U19.P2 27.34,84.56 27.34,85.18 25.44,87.08 25.44,91.99 25.84,92.39 25.84,113.22 26.21,113.59 29.64,113.59 29.86,113.81 29.86,114.09 29.63,114.32 28.04,114.32 27.64,114.72 27.64,115.29 28.04,115.69 29.66,115.69 29.86,115.89 29.86,116.18 29.66,116.38 28.04,116.38 27.66,116.75 27.66,122.73 27.55,122.84 26.13,122.84 25.72,123.25 25.72,123.97 26.09,124.34 28.67,124.34 28.87,124.54 28.87,124.83 28.67,125.03 27.11,125.03 26.71,125.43 26.71,126 27.11,126.4 29.3,126.4 29.5,126.6 29.5,126.88 29.3,127.08 27.44,127.08 27.04,127.49 27.04,128.05 27.44,128.46 29.3,128.46 29.5,128.66 29.5,129.45 29.3,129.65 28.8,129.65 28.3,130.16 28.3,131.17 28.83,131.7 32.77,131.7 33.25,131.21 J21.3
MIPI_CSI0_CLK1_N: length 77.3
  TOP w0.114: J21.14 35.75,134.92 35.83,135 35.83,135.49 35.5,135.82 35.31,135.82 35.25,135.76 35.06,135.76 34.92,135.89 34.92,136.08 34.99,136.14 34.99,136.33 34.8,136.53 34.11,136.53 33.97,136.39 33.97,136.28 33.84,136.14 33.65,136.14 33.52,136.28 33.52,136.39 33.38,136.53 28.04,136.53 22.01,130.49 22.01,107.15 22.21,106.95 22.43,106.95 22.83,106.54 22.83,105.98 22.43,105.57 22.21,105.57 22.01,105.37 22.01,105.09 22.21,104.89 22.43,104.89 22.83,104.49 22.83,103.92 22.43,103.52 22.21,103.52 22.01,103.32 22.01,103.03 22.21,102.83 22.43,102.83 22.83,102.43 22.83,101.86 22.43,101.46 22.21,101.46 22.01,101.26 22.01,91.46 22.35,91.11 22.35,89.28 21.95,88.87 20.78,88.87 20.58,88.67 20.58,88.39 20.78,88.19 21.99,88.19 22.39,87.79 22.39,87.22 21.99,86.82 21.5,86.82 21.3,86.62 21.3,86.33 21.5,86.13 21.95,86.13 22.35,85.73 22.35,85.34 24.43,83.26 26.69,83.26 U19.R4
MIPI_CSI0_CLK1_P: length 77.4
  TOP w0.114: J21.16 36.25,134.92 36.18,135 36.18,135.63 34.94,136.87 27.9,136.87 21.67,130.63 21.67,107 22.07,106.6 22.29,106.6 22.49,106.4 22.49,106.12 22.29,105.92 22.07,105.92 21.67,105.52 21.67,104.95 22.07,104.55 22.29,104.55 22.49,104.34 22.49,104.06 22.29,103.86 22.07,103.86 21.67,103.46 21.67,102.89 22.07,102.49 22.29,102.49 22.49,102.29 22.49,102 22.29,101.8 22.07,101.8 21.67,101.4 21.67,91.31 22.01,90.97 22.01,89.42 21.81,89.22 20.63,89.22 20.23,88.82 20.23,88.25 20.63,87.85 21.85,87.85 22.05,87.64 22.05,87.36 21.85,87.16 21.36,87.16 20.95,86.76 20.95,86.19 21.36,85.79 21.81,85.79 22.01,85.59 22.01,85.2 24.29,82.92 26.35,82.92 U19.T4
MIPI_CSI0_CLK2_N: length 77.4
  TOP w0.114: J21.25 38.75,129.29 38.91,129.13 38.91,128.39 38.78,128.26 38.69,128.26 38.56,128.13 38.56,127.94 38.69,127.8 38.78,127.8 38.91,127.67 38.91,127.48 38.78,127.35 38.69,127.35 38.56,127.21 38.56,127.02 38.69,126.89 38.78,126.89 38.91,126.75 38.91,126.34 39.48,125.77 47.33,125.77 48.13,124.97 48.13,122.66 46.09,120.61 44.94,120.61 44.62,120.29 44.62,119.29 44.42,119.09 44.14,119.09 43.94,119.29 43.94,120.25 43.54,120.65 42.97,120.65 42.57,120.25 42.57,119.29 42.37,119.09 42.08,119.09 41.88,119.29 41.88,121.67 41.25,122.3 36.74,122.3 35.68,121.25 34.78,121.25 34.23,120.69 34.23,104.18 32.9,102.86 30.72,102.86 30.25,102.39 30.25,84.9 U19.K1
MIPI_CSI0_CLK2_P: length 77.3
  TOP w0.114: U19.K2 30.59,84.56 30.59,102.25 30.86,102.51 33.05,102.51 34.57,104.04 34.57,120.55 34.92,120.9 35.83,120.9 36.88,121.96 41.11,121.96 41.54,121.53 41.54,119.15 41.94,118.75 42.51,118.75 42.91,119.15 42.91,120.11 43.11,120.31 43.39,120.31 43.6,120.11 43.6,119.15 44,118.75 44.57,118.75 44.97,119.15 44.97,120.15 45.09,120.27 46.23,120.27 48.48,122.52 48.48,125.11 47.48,126.11 39.62,126.11 39.25,126.48 J21.27
MIPI_CSI0_D0_N: length 77.2
  TOP w0.114: J21.4 33.25,132.95 32.77,132.46 30.44,132.46 30.04,132.86 30.04,133.82 29.84,134.02 29.55,134.02 29.35,133.82 29.35,132.86 28.94,132.45 28.31,132.45 27.94,132.82 27.53,132.82 26.28,131.57 26.28,131.28 27.5,130.07 27.5,129.55 27.03,129.09 26.53,129.09 25.31,130.31 25.03,130.31 24.21,129.49 24.21,128.6 24.41,128.4 25.89,128.4 26.29,128 26.29,127.43 25.89,127.03 24.41,127.03 24.21,126.83 24.21,126.5 24.41,126.3 25.56,126.3 25.96,125.9 25.96,125.33 25.56,124.93 24.41,124.93 24.21,124.73 24.21,120.95 24.51,120.65 24.97,120.65 25.25,120.93 25.25,121.55 25.65,121.96 26.49,121.96 26.87,121.57 26.87,115.06 26.49,114.68 25.55,114.68 25.1,114.22 25.1,100.41 24.21,99.52 24.21,92.36 24.64,91.93 24.64,86 26.07,84.56 26.69,84.56 U19.R2
MIPI_CSI0_D0_P: length 77.2
  TOP w0.114: U19.T2 26.35,84.22 25.93,84.22 24.3,85.85 24.3,86.23 24,86.52 24,86.71 24.3,87 24.3,91.78 23.86,92.21 23.86,99.66 24.75,100.55 24.75,114.37 25.41,115.02 26.35,115.02 26.53,115.2 26.53,121.43 26.35,121.62 25.8,121.62 25.59,121.41 25.59,120.79 25.11,120.31 24.37,120.31 23.86,120.81 23.86,124.87 24.26,125.27 25.41,125.27 25.62,125.47 25.62,125.75 25.41,125.96 24.26,125.96 23.86,126.36 23.86,126.97 24.26,127.37 25.75,127.37 25.95,127.57 25.95,127.86 25.75,128.06 24.26,128.06 23.86,128.46 23.86,129.63 24.89,130.65 25.45,130.65 26.68,129.43 26.89,129.43 27.15,129.69 27.15,129.93 25.94,131.14 25.94,131.71 27.39,133.16 28.08,133.16 28.45,132.79 28.8,132.79 29.01,133 29.01,133.96 29.41,134.37 29.98,134.37 30.38,133.96 30.38,133 30.58,132.8 32.62,132.8 32.75,132.93 J21.2
MIPI_CSI0_D1_N: length 77.4
  TOP w0.114: U19.N1 28.33,84.9 28.33,85.84 26.89,87.29 26.89,89.02 27.02,89.16 27.09,89.16 27.23,89.29 27.23,89.48 27.09,89.62 27.02,89.62 26.89,89.75 26.89,89.94 27.02,90.07 27.09,90.07 27.23,90.21 27.23,90.4 27.09,90.53 27.02,90.53 26.89,90.66 26.89,91.4 27.3,91.82 27.3,105.51 27.58,105.79 30.91,105.79 31.29,106.17 31.29,106.91 30.89,107.31 27.48,107.31 27.28,107.51 27.28,107.8 27.48,108 30.89,108 31.29,108.4 31.29,108.97 30.89,109.37 27.48,109.37 27.28,109.57 27.28,109.85 27.48,110.06 29.34,110.06 29.74,110.46 29.74,111.03 29.32,111.45 27.46,111.45 27.28,111.63 27.28,111.97 27.46,112.15 30.74,112.15 31.29,112.7 31.29,117.42 30.9,117.82 29.3,117.82 29.1,118.02 29.1,122.62 29.37,122.9 30.59,122.9 30.99,123.3 30.99,124.06 30.31,124.74 30.31,125.31 30.99,125.98 30.99,129.03 31.17,129.22 31.69,129.22 32.35,128.56 34.07,128.56 34.75,129.24 J21.9
MIPI_CSI0_D1_P: length 77.3
  TOP w0.114: J21.7 34.25,129.23 33.93,128.91 32.49,128.91 31.83,129.56 31.03,129.56 30.65,129.17 30.65,126.13 29.97,125.45 29.97,124.59 30.65,123.92 30.65,123.44 30.44,123.24 29.23,123.24 28.75,122.76 28.75,117.88 29.15,117.48 30.76,117.48 30.95,117.28 30.95,112.84 30.6,112.49 27.31,112.49 26.94,112.12 26.94,111.49 27.31,111.11 29.17,111.11 29.4,110.88 29.4,110.6 29.2,110.4 27.34,110.4 26.94,110 26.94,109.43 27.34,109.03 30.75,109.03 30.95,108.83 30.95,108.54 30.75,108.34 27.34,108.34 26.94,107.94 26.94,107.37 27.34,106.97 30.75,106.97 30.95,106.77 30.95,106.31 30.77,106.13 27.44,106.13 26.96,105.65 26.96,91.96 26.54,91.54 26.54,87.14 27.99,85.7 27.99,84.56 U19.N2
MIPI_CSI0_D2_N: length 77.4
  TOP w0.114: U19.T3 26.35,83.57 25.4,83.57 23.14,85.83 23.14,91.39 22.76,91.77 22.76,100.13 23.66,101.03 23.66,107.72 23.46,107.92 23.19,107.92 22.78,108.32 22.78,108.89 23.19,109.29 23.46,109.29 23.66,109.49 23.66,109.78 23.46,109.98 23.19,109.98 22.78,110.38 22.78,110.95 23.19,111.35 23.46,111.35 23.66,111.55 23.66,111.83 23.46,112.04 23.19,112.04 22.76,112.46 22.76,113.27 23.16,113.67 23.46,113.67 23.66,113.87 23.66,114.16 23.46,114.36 23.16,114.36 22.76,114.76 22.76,115.96 23.16,116.36 25.19,116.36 25.39,116.56 25.39,116.85 25.19,117.05 23.16,117.05 22.76,117.45 22.76,118.02 23.16,118.42 25.19,118.42 25.39,118.62 25.39,118.9 25.19,119.1 23.16,119.1 22.76,119.51 22.76,130.18 28.05,135.47 34.33,135.47 34.68,135.12 34.68,134.62 34.75,134.54 J21.10
MIPI_CSI0_D2_P: length 77.4
  TOP w0.114: J21.8 34.25,134.58 34.33,134.66 34.33,134.98 34.19,135.13 32.26,135.13 32.13,134.99 32.13,134.88 31.99,134.75 31.8,134.75 31.67,134.88 31.67,134.99 31.54,135.13 31.35,135.13 31.21,134.99 31.21,134.88 31.08,134.75 30.89,134.75 30.76,134.88 30.76,134.99 30.62,135.13 28.19,135.13 23.1,130.04 23.1,119.65 23.3,119.45 25.33,119.45 25.73,119.04 25.73,118.48 25.33,118.07 23.3,118.07 23.1,117.87 23.1,117.59 23.3,117.39 25.33,117.39 25.73,116.99 25.73,116.42 25.33,116.02 23.3,116.02 23.1,115.82 23.1,114.9 23.3,114.7 23.6,114.7 24,114.3 24,113.73 23.6,113.33 23.3,113.33 23.1,113.13 23.1,112.6 23.33,112.38 23.6,112.38 24,111.98 24,111.41 23.6,111.01 23.33,111.01 23.13,110.81 23.13,110.52 23.33,110.32 23.6,110.32 24,109.92 24,109.35 23.6,108.95 23.33,108.95 23.13,108.75 23.13,108.46 23.33,108.26 23.6,108.26 24,107.86 24,100.89 23.1,99.99 23.1,91.91 23.48,91.53 23.48,85.97 25.54,83.91 26.69,83.91 U19.R3
MIPI_CSI0_D3_N: length 77.3
  TOP w0.114: J21.20 37.25,134.92 37.41,135.07 37.41,136.07 37.13,136.35 36.94,136.35 36.88,136.28 36.69,136.28 36.56,136.42 36.56,136.61 36.62,136.67 36.62,136.86 36.49,137 36.3,137 36.23,136.93 36.04,136.93 35.91,137.07 35.91,137.25 35.97,137.32 35.97,137.51 35.81,137.67 27.61,137.67 20.92,130.98 20.92,92.93 19.48,91.49 19.48,86.49 23.36,82.61 26.69,82.61 U19.R5
MIPI_CSI0_D3_P: length 77.4
  TOP w0.114: U19.T5 26.35,82.27 23.21,82.27 19.14,86.34 19.14,91.63 20.57,93.07 20.57,131.12 27.47,138.01 35.96,138.01 37.75,136.21 J21.22
MIPI_CSI0_D4_N: length 77.2
  TOP w0.114: J21.21 37.75,125.34 38.07,125.02 46.92,125.02 47.37,124.56 47.37,123.85 46.88,123.36 46.27,123.36 46.07,123.15 46.07,121.81 45.67,121.41 45.1,121.41 44.7,121.81 44.7,123.18 44.5,123.38 44.21,123.38 44.01,123.18 44.01,121.81 43.61,121.41 43.04,121.41 42.64,121.81 42.64,122.23 41.68,123.19 36.55,123.19 35.41,122.05 33.78,122.05 33.48,121.74 33.48,104.85 32.23,103.61 29.82,103.61 29.49,103.28 29.49,90.45 29.21,90.17 29.21,87.76 29.94,87.02 29.94,84.56 U19.L2
MIPI_CSI0_D4_P: length 77.3
  TOP w0.114: U19.L1 29.6,84.9 29.6,86.88 28.87,87.61 28.87,90.31 29.15,90.59 29.15,103.42 29.68,103.95 32.09,103.95 33.13,104.99 33.13,121.88 33.64,122.39 35.27,122.39 36.41,123.53 41.82,123.53 42.98,122.37 42.98,121.96 43.18,121.75 43.47,121.75 43.67,121.96 43.67,123.32 44.07,123.72 44.64,123.72 45.04,123.32 45.04,121.96 45.24,121.75 45.53,121.75 45.73,121.96 45.73,123.3 46.13,123.7 46.74,123.7 47.03,123.99 47.03,124.42 46.77,124.68 37.93,124.68 37.41,125.19 37.41,126.86 37.28,126.99 37.19,126.99 37.06,127.13 37.06,127.32 37.19,127.45 37.28,127.45 37.41,127.58 37.41,127.77 37.28,127.91 37.19,127.91 37.06,128.04 37.06,128.23 37.19,128.36 37.28,128.36 37.41,128.5 37.41,129.09 37.25,129.24 J21.19
MIPI_CSI0_D5_N: length 77.4
  TOP w0.114: U19.M2 28.64,84.56 28.64,86.29 27.72,87.21 27.72,91.07 28.05,91.4 28.05,104.49 28.61,105.04 31.53,105.04 32.04,105.55 32.04,109.97 31.88,110.12 30.86,110.12 30.49,110.49 30.49,111.06 30.84,111.41 31.8,111.41 32.04,111.65 32.04,118.48 31.86,118.66 30.25,118.66 29.84,119.06 29.84,119.63 30.25,120.03 31.82,120.03 32.02,120.23 32.02,120.52 31.82,120.72 30.25,120.72 29.84,121.12 29.84,121.69 30.25,122.09 31.56,122.09 31.75,122.28 31.75,123.11 32.15,123.52 34.84,123.52 35.04,123.72 35.04,124 34.84,124.2 32.15,124.2 31.75,124.6 31.75,125.17 32.15,125.57 36.03,125.57 36.23,125.77 36.23,126.06 36.03,126.26 32.15,126.26 31.75,126.66 31.75,127.36 32.2,127.81 35.63,127.81 35.83,128.01 35.83,129.16 35.75,129.24 J21.13
MIPI_CSI0_D5_P: length 77.3
  TOP w0.114: U19.M1 28.98,84.9 28.98,86.44 28.07,87.35 28.07,88.91 28.2,89.05 28.26,89.05 28.4,89.18 28.4,89.37 28.26,89.5 28.2,89.5 28.07,89.64 28.07,89.83 28.2,89.96 28.26,89.96 28.4,90.1 28.4,90.28 28.26,90.42 28.2,90.42 28.07,90.55 28.07,90.93 28.4,91.26 28.4,104.34 28.75,104.7 31.67,104.7 32.38,105.41 32.38,110.11 32.03,110.47 31,110.47 30.84,110.63 30.84,110.91 30.99,111.06 31.94,111.06 32.38,111.51 32.38,118.62 32,119 30.39,119 30.19,119.2 30.19,119.49 30.39,119.69 31.96,119.69 32.36,120.09 32.36,120.66 31.96,121.06 30.39,121.06 30.19,121.26 30.19,121.55 30.39,121.75 31.7,121.75 32.09,122.14 32.09,122.97 32.29,123.17 34.98,123.17 35.38,123.58 35.38,124.14 34.98,124.55 32.29,124.55 32.09,124.75 32.09,125.03 32.29,125.23 36.17,125.23 36.58,125.63 36.58,126.2 36.17,126.6 32.29,126.6 32.09,126.8 32.09,127.22 32.35,127.47 35.78,127.47 36.18,127.87 36.18,129.16 36.25,129.24 J21.15
MIPI_DSI_CLK0_N: length 38
  TOP w0.114: U19.R9 26.69,80.01 22.74,80.01 21.97,79.25 18.9,79.25 16.65,81.5 14.09,81.5 v1(13.72,81.87) ; J22.19 8.57,97.91 8.65,97.99 9.54,97.99 9.65,97.87 v1(9.65,97.65)
  BOTTOM w0.114: v1(13.72,81.87) 13.38,81.53 12.95,81.53 8.13,86.36 8.13,97.79 8.33,97.99 9.54,97.99 9.65,97.87 v1(9.65,97.65)
MIPI_DSI_CLK0_P: length 38
  TOP w0.114: v1(13.72,80.85) 14.01,81.15 16.51,81.15 18.76,78.91 22.11,78.91 22.88,79.67 26.35,79.67 U19.T9 ; v1(9.65,98.67) 9.32,98.33 8.65,98.33 8.57,98.41 J22.20
  BOTTOM w0.114: v1(13.72,80.85) 13.38,81.19 12.81,81.19 7.79,86.22 7.79,97.93 8.18,98.33 9.32,98.33 v1(9.65,98.67)
MIPI_DSI_D0_N: length 38
  TOP w0.114: J22.22 8.57,99.41 8.65,99.49 11.44,99.49 11.56,99.37 v1(11.56,99.19) ; v1(13.72,84.16) 14.05,83.82 17.42,83.82 20.58,80.66 26.69,80.66 U19.R8
  BOTTOM w0.114: v1(11.56,99.19) 11.56,99.41 11.4,99.57 11.08,99.57 10.92,99.41 10.92,97.41 10.03,96.52 10.03,86.61 12.83,83.82 13.38,83.82 v1(13.72,84.16)
MIPI_DSI_D0_P: length 38.1
  TOP w0.114: J22.23 8.57,99.91 8.65,99.83 11.18,99.83 v1(11.56,100.2) ; v1(13.72,83.14) 14.05,83.48 17.28,83.48 20.44,80.32 26.35,80.32 U19.T8
  BOTTOM w0.114: v1(11.56,100.2) 11.26,99.91 10.94,99.91 10.58,99.55 10.58,97.55 9.69,96.66 9.69,86.47 12.68,83.48 13.38,83.48 v1(13.72,83.14)
MIPI_DSI_D1_N: length 37.9
  TOP w0.114: v1(6.58,96.15) 6.92,96.49 7.13,96.49 7.2,96.41 J22.16 ; v1(13.72,79.58) 14.05,79.25 16,79.25 17.23,78.02 22.29,78.02 23.63,79.36 26.69,79.36 U19.R10
  BOTTOM w0.114: v1(6.58,96.15) 6.58,96.37 6.43,96.52 6.2,96.52 5.97,96.29 5.97,94.61 6.95,93.64 6.95,85.51 13.25,79.21 13.55,79.21 13.72,79.38 v1(13.72,79.58)
MIPI_DSI_D1_P: length 38
  TOP w0.114: v1(13.72,78.57) 14.05,78.91 15.86,78.91 17.09,77.67 22.43,77.67 23.77,79.02 26.35,79.02 U19.T10 ; J22.17 7.2,96.91 7.13,96.83 6.92,96.83 v1(6.58,97.17)
  BOTTOM w0.114: v1(13.72,78.57) 13.42,78.87 13.1,78.87 6.6,85.37 6.6,93.49 5.63,94.47 5.63,96.43 6.06,96.86 6.27,96.86 v1(6.58,97.17)
MIPI_DSI_D2_N: length 37.9
  TOP w0.114: J22.13 8.57,94.91 8.73,95.07 10.93,95.07 11.05,94.95 v1(11.05,94.78) ; v1(13.72,85.43) 13.72,85.65 13.83,85.76 16.62,85.76 21.42,80.97 26.35,80.97 U19.T7
  BOTTOM w0.114: v1(13.72,85.43) 13.72,85.6 13.42,85.89 12.81,85.89 12.36,86.34 12.36,87.49 12.16,87.69 11.2,87.69 10.79,88.09 10.79,88.66 11.2,89.06 12.28,89.06 12.48,89.26 12.48,89.55 12.28,89.75 11.2,89.75 10.79,90.15 10.79,90.72 11.2,91.12 12.41,91.12 12.61,91.32 12.61,91.61 12.41,91.81 11.2,91.81 10.79,92.21 10.79,92.78 11.2,93.18 11.78,93.18 11.98,93.38 11.98,95 11.73,95.25 11.28,95.25 11.05,95.02 v1(11.05,94.78)
MIPI_DSI_D2_P: length 37.9
  TOP w0.114: J22.14 10.66,95.41 v1(11.05,95.79) ; v1(13.72,86.44) 14.05,86.11 16.76,86.11 21.56,81.31 26.69,81.31 U19.R7
  BOTTOM w0.114: v1(11.05,95.79) 11.25,95.59 11.87,95.59 12.32,95.14 12.32,93.24 11.92,92.83 11.34,92.83 11.14,92.63 11.14,92.35 11.34,92.15 12.55,92.15 12.95,91.75 12.95,91.18 12.55,90.78 11.34,90.78 11.14,90.58 11.14,90.29 11.34,90.09 12.43,90.09 12.83,89.69 12.83,89.12 12.43,88.72 11.34,88.72 11.14,88.52 11.14,88.24 11.34,88.03 12.3,88.03 12.7,87.63 12.7,86.49 12.95,86.23 13.51,86.23 v1(13.72,86.44)
MIPI_DSI_D3_N: length 38
  TOP w0.114: v1(13.72,88.73) 14.05,88.39 16.03,88.39 22.46,81.96 26.69,81.96 U19.R6 ; J22.25 8.54,100.91 8.62,100.99 9.76,100.99 9.93,100.81 v1(9.93,100.65)
  BOTTOM w0.114: v1(9.93,100.65) 9.93,100.87 10.15,101.09 12.21,101.09 13.5,99.81 13.5,98.78 13.3,98.58 12.85,98.58 12.45,98.18 12.45,97.61 12.85,97.21 13.3,97.21 13.5,97.01 13.5,92.69 15.24,90.95 15.24,88.77 14.86,88.39 14.05,88.39 v1(13.72,88.73)
MIPI_DSI_D3_P: length 38
  TOP w0.114: J22.26 8.54,101.41 8.62,101.33 9.59,101.33 v1(9.93,101.67) ; U19.T6 26.35,81.62 22.32,81.62 15.89,88.05 14.05,88.05 v1(13.72,87.71)
  BOTTOM w0.114: v1(9.93,101.67) 10.16,101.43 12.36,101.43 13.84,99.95 13.84,98.64 13.44,98.24 12.99,98.24 12.79,98.04 12.79,97.75 12.99,97.55 13.44,97.55 13.84,97.15 13.84,92.84 15.58,91.1 15.58,88.63 15,88.05 14.05,88.05 v1(13.72,87.71)
MIPI_DSI_D_RST: length 29.3
  TOP w0.127: v1(33.66,101.85) 33.78,101.73 R214.2 ; v1(19.68,105.06) 17.03,102.41 J22.28
  BOTTOM w0.127: v1(33.66,101.85) 30.45,105.06 v1(19.68,105.06)
MIPI_DSI_LCD_EN: length 31.2
  TOP w0.127: R213.2 v1(34.92,101.85) ; J22.29 9.56,102.91 9.65,103 16.51,103 v1(19.68,106.17)
  BOTTOM w0.127: v1(19.68,106.17) 30.61,106.17 v1(34.92,101.85)
MIPI_DSI_T_INT: length 30.4
  TOP w0.127: v1(19.68,102.62) 13.21,96.14 13.21,94.23 11.68,92.71 9.27,92.71 8.57,93.41 J22.10 ; R215.2 v1(31.5,101.73)
  BOTTOM w0.127: v1(31.5,101.73) 30.61,102.62 v1(19.68,102.62)
MIPI_DSI_T_RST: length 32.6
  TOP w0.127: J22.11 8.83,93.91 9.53,93.22 11.43,93.22 12.7,94.49 12.7,96.76 v1(19.68,103.76) ; R216.2 v1(32.64,101.85)
  BOTTOM w0.127: v1(19.68,103.76) 30.73,103.76 v1(32.64,101.85)
NVCC_SD: length 94.4
  TOP w0.254: U19.N8 v3(27.99,80.66)
  TOP w0.305: R225.2 v1(43.43,113.79)
  TOP w0.381: R227.2 v1(52.83,113.79)
  ART03 w0.305: v3(27.99,80.66) 26.54,82.11 26.54,84.45 28.02,85.93 28.02,96.35 v1(25.05,99.31)
  BOTTOM w0.254: C305.1 27.43,81.15 27.92,80.66 v3(27.99,80.66)
  BOTTOM w0.305: 14.1,104.39 14.1,105.28 14.61,105.79 14.61,108.46 v1(15.37,109.22) ; v1(12.57,116.71) R161.1 R160.1 ; R157.1 v1(16.38,116.71) ; v1(25.05,99.31) 20.83,99.31 18.29,101.85 18.29,116.33 v1(17.91,116.71) R158.1 ; R209.1 13.97,111 ; R156.1 v1(14.1,116.71)
  BOTTOM w0.381: v1(19.46,116.71) 19.46,116.99 R159.1 24.13,113.79 v1(43.43,113.79) 44.32,112.9 51.94,112.9 v1(52.83,113.79)
  vias: v1(13.59,112.14) v1(13.59,111.12)
PG_0V8: length 108.5
  TOP w0.254: R35.1 C72.2 v1(21.84,20.83) 21.84,21.67 22.15,21.98 U7.7
  TOP w0.305: R42.2 13.72,47.75 v1(15.49,49.53) 15.88,49.92 U8.2 ; U9.7 65.16,68.78 64.72,69.22 v1(62.87,69.22) 62.74,69.09 C96.2 R49.1
  ART03 w0.254: v1(62.87,69.22) 62.87,70.99 61.79,72.07 59.63,72.07 57.91,70.36 51.18,70.36 49.91,69.09 49.91,66.55 43.81,60.45 27.43,60.45 25.02,58.04 25.02,53.09 22.61,50.67 16.64,50.67 v1(15.49,49.53) 15.49,47.75 19.05,44.2 19.05,28.57 20.45,27.18 20.45,23.62 21.84,22.23 v1(21.84,20.83)
PG_1V8: length 73.5
  TOP w0.305: v1(40.26,45.72) 38.77,45.72 38.46,46.02 U15.5 ; v1(62.1,62.87) R47.2 62.99,63.75 65.16,65.92 U9.2 ; v1(35.05,28.07) 35.23,28.25 U16.2 ; v1(59.31,67.67) 59.29,67.65 U17.4
  ART03 w0.254: v1(35.05,28.07) 34.04,29.08 34.04,30.86 36.63,33.45 36.63,36.88 40.26,40.51 v1(40.26,45.72) 40.39,45.85 40.39,51.82 43.05,54.48 43.05,58.04 48.21,63.2 49.23,63.2 51.94,65.91 51.94,67.44 54.23,69.72 v1(54.99,69.72)
  ART03 w0.305: v1(62.1,62.87) 62.1,65.79 60.58,67.31 59.66,67.31 v1(59.31,67.67)
  BOTTOM w0.305: v1(54.99,69.72) 57.66,69.72 58.55,68.83 R80.1 C152.1 59.08,67.44 v1(59.31,67.67)
PG_3V3: length 126.8
  TOP w0.254: U7.2 25.01,21.98 v1(25.53,21.46) 27.18,19.81 R37.2 ; C103.1 R50.1 v1(21.08,30.99) 21.07,31 U10.4 ; v1(1.91,89.15) 1.14,88.39 1.14,53.72 2.67,52.2 7.24,52.2 8.26,51.18 8.26,49.53 13.72,44.07 18.92,44.07 20.64,42.35 v1(24,42.35) 29.53,42.35 29.97,42.8 R60.2
  ART03 w0.254: v1(25.53,21.46) 24.26,22.73 24.26,27.81 v1(21.08,30.99) 21.08,33.4 24,36.32 v1(24,42.35)
  BOTTOM w0.254: R211.1 7.87,111 1.91,105.03 v1(1.91,89.15)
PW_EN: length 162.7
  TOP w0.254: v1(43.94,22.73) 48.77,22.73 50.56,24.52 51.69,24.52 51.94,24.78 R14.2 R17.1 C35.2 v1(52.96,27.3) 53.21,27.06 U4.15 ; R28.1 42.42,30.35 42.09,30.02 40.06,30.02 39.75,29.72 39.75,25.53 39.12,24.89 33.27,24.89 31.04,27.13 14.78,27.13 13.34,28.57 R67.1 C132.1 12.95,30.61 v1(12.95,31.11) 12.95,31.24 13.76,32.04 U14.4 ; U3.4 v1(65.66,47.12) 66.67,47.12 C23.1 R8.1 ; U5.4 54.73,48.14 54.86,48.01 v1(55.24,48.01)
  TOP w0.305: U6.7 45.47,31.19 45.17,31.5 v1(43.56,31.5) 43.43,31.62 C60.2 R28.1 ; R43.1 C84.2 v1(13.97,53.09) 15.57,53.09 15.88,52.78 U8.7
  ART03 w0.254: v1(12.95,31.11) 13.08,31.24 13.08,52.2 v1(13.97,53.09) ; v1(52.96,27.3) 52.63,26.97 52.63,7.32 53.98,5.97 53.98,3.17 52.7,1.91 50.16,1.91 ; v1(55.24,48.01) 51.18,43.94 51.18,42.67 44.2,35.69 44.2,32.13 v1(43.56,31.5) 43.94,31.11 v1(43.94,22.73)
  BOTTOM w0.254: v1(65.66,47.12) 64.52,48.26 55.5,48.26 v1(55.24,48.01) C50.1 R23.1
QSPI0_CLK: length 29.6
  TOP w0.127: U19.E1 33.52,86.91 34.51,87.9 34.51,96.23 36.23,97.95 36.23,102.59 39.42,105.79 39.63,105.79 39.9,105.52 40.11,105.52 40.26,105.67 40.26,105.88 39.99,106.15 39.99,106.36 40.14,106.51 40.35,106.51 40.62,106.24 40.83,106.24 40.98,106.39 40.98,106.6 40.71,106.87 40.71,107.08 41.58,107.95 U37.6
